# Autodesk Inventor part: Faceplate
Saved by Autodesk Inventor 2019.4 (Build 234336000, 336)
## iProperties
Created: 2021-06
Part Number: Faceplate
Material: Generic
Document SubType Name: Modeling
Designer: Administrator
Density: 1 g/cm^3
Appearance: Default
Title: Faceplate v7
Author: Administrator
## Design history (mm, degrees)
feature "Body1"
body "Solid1"
